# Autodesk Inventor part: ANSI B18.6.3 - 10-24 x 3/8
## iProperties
Comments: To add or edit properties for Autodesk Inventor files, use iProperties.
Created: 2004-08
Part Number: ANSI B18.6.3 - 10-24 x 3/8
Vendor: Autodesk Inc.
Document SubType Name: Modeling
Designer: John Blackburn
Material: Default
Description: Slotted Flat Countersunk Head Machine Screw
Standard: ANSI B18.6.3
Alert: To add or edit properties for Autodesk Inventor files, use iProperties.
Control State: 0
Master: False
Checked Out: False
Shininess: 64.0
Length Units: 11272
Angle Units: 11279
Time Units: 11290
Mass Units: 11286
Length Display Precision: 3
Angle Display Precision: 2
Compacted: True
EGR: 3
Classification: un/spsc 31161513
Density: 0.0
Volumn: 0.0
Area: 0.0
PropertySet Name: Model Information
Author: John Blackburn
Revision Number: 8
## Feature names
1. Body [Revolution]
2. Slot [Extrusion]
